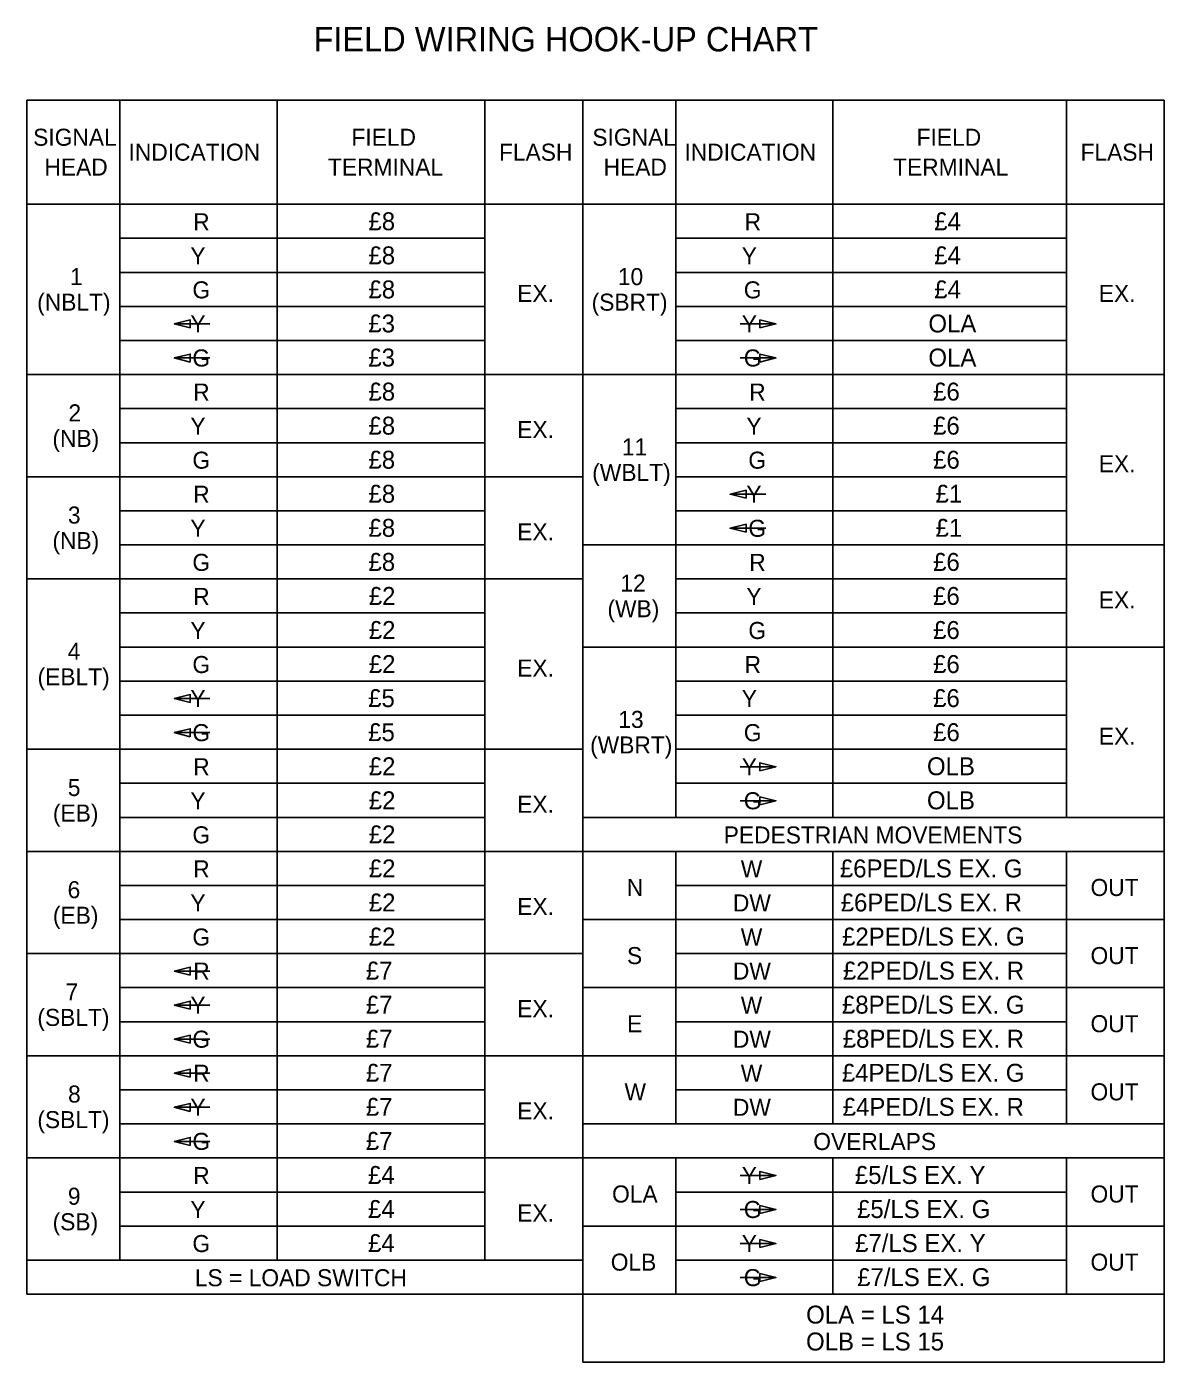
# Model space of a CAD drawing. Extents: x 680 to 2132, y 0 to 656.
# Drawn here: x 1954.6 to 2132.2, y 74.2 to 282.8 of the extents above; entities that cross this region are included whole.
import ezdxf

# ---------------------------------------------------------------- set-up
doc = ezdxf.new("R2010")
doc.units = 0
for name, color, linetype in [('SH_Data', 7, 'Continuous'), ('SH_Text', 7, 'Continuous'), ('ST_Text', 7, 'Continuous')]:
    doc.layers.add(name, color=color, linetype=linetype)

msp = doc.modelspace()

# ---------------------------------------------------------------- linework, layer by layer
at = {"layer": 'SH_Data'}
for p, q in [((1977.6, 236.37), (1983.15, 236.37)), ((2071.56, 236.37), (2066, 236.37)), ((1977.6, 231.05), (1983.15, 231.05)), ((2071.56, 231.05), (2066, 231.05)), ((2064.41, 209.77), (2069.97, 209.77)), ((2064.41, 204.45), (2069.97, 204.45)), ((1977.6, 177.85), (1983.15, 177.85)), ((1977.6, 172.53), (1983.15, 172.53)), ((2071.56, 167.21), (2066, 167.21)), ((2071.56, 161.89), (2066, 161.89)), ((1977.6, 135.29), (1983.15, 135.29)), ((1977.6, 129.97), (1983.15, 129.97)), ((1977.6, 124.65), (1983.15, 124.65)), ((1977.6, 119.33), (1983.15, 119.33)), ((1977.6, 114.01), (1983.15, 114.01)), ((1977.6, 108.69), (1983.15, 108.69)), ((2071.56, 103.37), (2066, 103.37)), ((2071.56, 98.05), (2066, 98.05)), ((2071.56, 92.73), (2066, 92.73)), ((2071.56, 87.41), (2066, 87.41))]:
    msp.add_line(p, q, dxfattribs=at)
for points in [[(1980.1, 235.74), (1977.6, 236.37), (1980.1, 236.99)], [(2069.06, 235.74), (2071.56, 236.37), (2069.06, 236.99)], [(1980.1, 230.42), (1977.6, 231.05), (1980.1, 231.67)], [(2069.06, 230.42), (2071.56, 231.05), (2069.06, 231.67)], [(2066.91, 209.14), (2064.41, 209.77), (2066.91, 210.39)], [(2066.91, 203.82), (2064.41, 204.45), (2066.91, 205.07)], [(1980.1, 177.22), (1977.6, 177.85), (1980.1, 178.47)], [(1980.1, 171.9), (1977.6, 172.53), (1980.1, 173.15)], [(2069.06, 166.58), (2071.56, 167.21), (2069.06, 167.83)], [(2069.06, 161.26), (2071.56, 161.89), (2069.06, 162.51)], [(1980.1, 134.66), (1977.6, 135.29), (1980.1, 135.91)], [(1980.1, 129.34), (1977.6, 129.97), (1980.1, 130.59)], [(1980.1, 124.02), (1977.6, 124.65), (1980.1, 125.27)], [(1980.1, 118.7), (1977.6, 119.33), (1980.1, 119.95)], [(1980.1, 113.38), (1977.6, 114.01), (1980.1, 114.63)], [(1980.1, 108.06), (1977.6, 108.69), (1980.1, 109.31)], [(2069.06, 102.74), (2071.56, 103.37), (2069.06, 103.99)], [(2069.06, 97.42), (2071.56, 98.05), (2069.06, 98.67)], [(2069.06, 92.1), (2071.56, 92.73), (2069.06, 93.35)], [(2069.06, 86.78), (2071.56, 87.41), (2069.06, 88.03)]]:
    msp.add_lwpolyline(points, close=True, dxfattribs=at)
at = {"layer": 'ST_Text'}
for p, q in [((1954.58, 271.34), (2132.21, 271.34)), ((1954.58, 271.34), (1954.58, 84.82)), ((1969.13, 271.34), (1969.13, 90.14)), ((1993.66, 271.34), (1993.66, 90.14)), ((2026.11, 271.34), (2026.11, 90.14)), ((2041.39, 271.34), (2041.39, 74.18)), ((2055.95, 271.34), (2055.95, 159.3)), ((2080.47, 271.34), (2080.47, 159.3)), ((2116.92, 271.34), (2116.92, 159.3)), ((2132.21, 271.34), (2132.21, 74.18)), ((1954.58, 255.06), (2132.21, 255.06)), ((1969.13, 249.74), (2026.11, 249.74)), ((2055.95, 249.74), (2116.92, 249.74)), ((1969.13, 244.42), (2026.11, 244.42)), ((2055.95, 244.42), (2116.92, 244.42)), ((1969.13, 239.1), (2026.11, 239.1)), ((2055.95, 239.1), (2116.92, 239.1)), ((1969.13, 233.78), (2026.11, 233.78)), ((2055.95, 233.78), (2116.92, 233.78)), ((1954.58, 228.46), (2132.21, 228.46)), ((1969.13, 223.14), (2026.11, 223.14)), ((2055.95, 223.14), (2116.92, 223.14)), ((1969.13, 217.82), (2026.11, 217.82)), ((2055.95, 217.82), (2116.92, 217.82)), ((1954.58, 212.5), (2041.39, 212.5)), ((2055.95, 212.5), (2116.92, 212.5)), ((1969.13, 207.18), (2026.11, 207.18)), ((2055.95, 207.18), (2116.92, 207.18)), ((1969.13, 201.86), (2026.11, 201.86)), ((2041.39, 201.86), (2132.21, 201.86)), ((1954.58, 196.54), (2041.39, 196.54)), ((2055.95, 196.54), (2116.92, 196.54)), ((1969.13, 191.22), (2026.11, 191.22)), ((2055.95, 191.22), (2116.92, 191.22)), ((1969.13, 185.9), (2026.11, 185.9)), ((2041.39, 185.9), (2132.21, 185.9)), ((1969.13, 180.58), (2026.11, 180.58)), ((2055.95, 180.58), (2116.92, 180.58)), ((1969.13, 175.26), (2026.11, 175.26)), ((2055.95, 175.26), (2116.92, 175.26)), ((1954.58, 169.94), (2041.39, 169.94)), ((2055.95, 169.94), (2116.92, 169.94)), ((1969.13, 164.62), (2026.11, 164.62)), ((2055.95, 164.62), (2116.92, 164.62)), ((1969.13, 159.3), (2026.11, 159.3)), ((2041.39, 159.3), (2132.21, 159.3)), ((1954.58, 153.98), (2041.39, 153.98)), ((2041.39, 153.98), (2132.21, 153.98)), ((2055.95, 153.98), (2055.95, 111.42)), ((2080.47, 153.98), (2080.47, 111.42)), ((2116.92, 153.98), (2116.92, 111.42)), ((1969.13, 148.66), (2026.11, 148.66)), ((2055.95, 148.66), (2116.92, 148.66)), ((1969.13, 143.34), (2026.11, 143.34)), ((2041.39, 143.34), (2132.21, 143.34)), ((1954.58, 138.02), (2041.39, 138.02)), ((2055.95, 138.02), (2116.92, 138.02)), ((1969.13, 132.7), (2026.11, 132.7)), ((2041.39, 132.7), (2132.21, 132.7)), ((1969.13, 127.38), (2026.11, 127.38)), ((2055.95, 127.38), (2116.92, 127.38)), ((1954.58, 122.06), (2041.39, 122.06)), ((2041.39, 122.06), (2128.21, 122.06)), ((2041.39, 122.06), (2132.21, 122.06)), ((1969.13, 116.74), (2026.11, 116.74)), ((2055.95, 116.74), (2116.92, 116.74)), ((1969.13, 111.42), (2026.11, 111.42)), ((2041.39, 111.42), (2132.21, 111.42)), ((1954.58, 106.1), (2041.39, 106.1)), ((2041.39, 106.1), (2132.21, 106.1)), ((2055.95, 106.1), (2055.95, 84.82)), ((2080.47, 106.1), (2080.47, 84.82)), ((2116.92, 106.1), (2116.92, 84.82)), ((1969.13, 100.78), (2026.11, 100.78)), ((2055.95, 100.78), (2116.92, 100.78)), ((1969.13, 95.46), (2026.11, 95.46)), ((2041.39, 95.46), (2132.21, 95.46)), ((1954.58, 90.14), (2041.39, 90.14)), ((2055.95, 90.14), (2116.92, 90.14)), ((1954.58, 84.82), (2041.39, 84.82)), ((2041.39, 84.82), (2132.21, 84.82)), ((2041.39, 74.18), (2132.21, 74.18))]:
    msp.add_line(p, q, dxfattribs=at)

# ---------------------------------------------------------------- texts
at = {"layer": 'SH_Text'}
for s, height, p in [('FIELD WIRING HOOK-UP CHART', 3.8, (1999.36, 278.94)), ('£8', 2.8, (2007.94, 251)), ('£4', 2.8, (2096.28, 251)), ('£8', 2.8, (2007.94, 245.68)), ('£4', 2.8, (2096.28, 245.68)), ('£8', 2.8, (2007.94, 240.36)), ('£4', 2.8, (2096.28, 240.36)), ('£3', 2.8, (2007.92, 235.04)), ('OLA', 2.8, (2095.37, 235.04)), ('£3', 2.8, (2007.92, 229.72)), ('OLA', 2.8, (2095.37, 229.72)), ('£8', 2.8, (2007.94, 224.4)), ('£6', 2.8, (2096.11, 224.4)), ('£8', 2.8, (2007.94, 219.08)), ('£6', 2.8, (2096.11, 219.08)), ('£8', 2.8, (2007.94, 213.76)), ('£6', 2.8, (2096.11, 213.76)), ('£8', 2.8, (2007.94, 208.44)), ('£1', 2.8, (2096.49, 208.44)), ('£8', 2.8, (2007.94, 203.12)), ('£1', 2.8, (2096.49, 203.12)), ('£8', 2.8, (2007.94, 197.8)), ('£6', 2.8, (2096.11, 197.8)), ('£2', 2.8, (2007.99, 192.48)), ('£6', 2.8, (2096.11, 192.48)), ('£2', 2.8, (2007.99, 187.16)), ('£6', 2.8, (2096.11, 187.16)), ('£2', 2.8, (2007.99, 181.84)), ('£6', 2.8, (2096.11, 181.84)), ('£5', 2.8, (2007.89, 176.52)), ('£6', 2.8, (2096.11, 176.52)), ('£5', 2.8, (2007.89, 171.2)), ('£6', 2.8, (2096.11, 171.2)), ('£2', 2.8, (2007.99, 165.88)), ('OLB', 2.8, (2095.15, 165.88)), ('£2', 2.8, (2007.99, 160.56)), ('OLB', 2.8, (2095.15, 160.56)), ('£2', 2.8, (2007.99, 155.24)), ('£2', 2.8, (2007.99, 149.92)), ('£6PED/LS EX. G', 2.8, (2081.55, 149.92)), ('£2', 2.8, (2007.99, 144.6)), ('£6PED/LS EX. R', 2.8, (2081.68, 144.6)), ('£2', 2.8, (2007.99, 139.28)), ('£2PED/LS EX. G', 2.8, (2081.89, 139.28)), ('£7', 2.8, (2007.53, 133.96)), ('£2PED/LS EX. R', 2.8, (2082.02, 133.96)), ('£7', 2.8, (2007.53, 128.64)), ('£8PED/LS EX. G', 2.8, (2081.87, 128.64)), ('£7', 2.8, (2007.53, 123.32)), ('£8PED/LS EX. R', 2.8, (2082, 123.32)), ('£7', 2.8, (2007.53, 118)), ('£4PED/LS EX. G', 2.8, (2081.86, 118)), ('£7', 2.8, (2007.53, 112.68)), ('£4PED/LS EX. R', 2.8, (2081.99, 112.68)), ('£7', 2.8, (2007.53, 107.36)), ('£4', 2.8, (2007.87, 102.04)), ('£5/LS EX. Y', 2.8, (2083.89, 102.04)), ('£4', 2.8, (2007.87, 96.72)), ('£5/LS EX. G', 2.8, (2084.23, 96.72)), ('£4', 2.8, (2007.87, 91.4)), ('£7/LS EX. Y', 2.8, (2083.92, 91.4)), ('£7/LS EX. G', 2.8, (2084.25, 86.08)), ('OLA = LS 14', 2.8, (2076.28, 80.23)), ('OLB = LS 15', 2.8, (2076.27, 76.03))]:
    msp.add_text(s, height=height, dxfattribs=at).set_placement(p)
at = {"layer": 'ST_Text'}
for s, p in [('SIGNAL', (1955.58, 264.2)), ('FIELD', (2005.28, 264.2)), ('SIGNAL', (2042.9, 264.2)), ('FIELD', (2093.53, 264.2)), ('INDICATION', (1970.47, 261.87)), ('FLASH', (2028.32, 261.87)), ('INDICATION', (2057.28, 261.87)), ('FLASH', (2119.13, 261.87)), ('HEAD', (1957.34, 259.54)), ('TERMINAL', (2001.61, 259.54)), ('HEAD', (2044.66, 259.54)), ('TERMINAL', (2089.86, 259.54)), ('R', (1980.57, 251)), ('R', (2066.67, 251)), ('Y', (1980.13, 245.68)), ('Y', (2066.23, 245.68)), ('1', (1961.33, 242.43)), ('10', (2046.88, 242.43)), ('G', (1980.45, 240.36)), ('EX.', (2031.17, 239.81)), ('G', (2066.55, 240.36)), ('EX.', (2121.98, 239.81)), ('(NBLT)', (1956.21, 238.44)), ('(SBRT)', (2042.79, 238.44)), ('Y', (1980.13, 235.04)), ('Y', (2066.23, 235.04)), ('G', (1980.45, 229.72)), ('G', (2066.55, 229.72)), ('R', (1980.57, 224.4)), ('R', (2067.39, 224.4)), ('2', (1961.09, 221.15)), ('Y', (1980.13, 219.08)), ('EX.', (2031.17, 218.53)), ('Y', (2066.95, 219.08)), ('(NB)', (1958.59, 217.16)), ('11', (2047.51, 215.83)), ('G', (1980.45, 213.76)), ('G', (2067.26, 213.76)), ('EX.', (2121.98, 213.21)), ('(WBLT)', (2042.88, 211.84)), ('R', (1980.57, 208.44)), ('Y', (2066.95, 208.44)), ('3', (1961.01, 205.19)), ('Y', (1980.13, 203.12)), ('EX.', (2031.17, 202.57)), ('G', (2067.26, 203.12)), ('(NB)', (1958.59, 201.2)), ('G', (1980.45, 197.8)), ('R', (2067.39, 197.8)), ('12', (2047.27, 194.55)), ('R', (1980.57, 192.48)), ('Y', (2066.95, 192.48)), ('EX.', (2121.98, 191.93)), ('(WB)', (2045.26, 190.56)), ('G', (2067.26, 187.16)), ('Y', (1980.13, 187.16)), ('4', (1960.97, 183.91)), ('G', (1980.45, 181.84)), ('EX.', (2031.17, 181.29)), ('R', (2066.67, 181.84)), ('(EBLT)', (1956.27, 179.92)), ('Y', (1980.13, 176.52)), ('Y', (2066.23, 176.52)), ('13', (2046.95, 173.27)), ('G', (1980.45, 171.2)), ('G', (2066.55, 171.2)), ('EX.', (2121.98, 170.65)), ('(WBRT)', (2042.55, 169.28)), ('R', (1980.57, 165.88)), ('Y', (2066.23, 165.88)), ('5', (1960.99, 162.63)), ('Y', (1980.13, 160.56)), ('G', (2066.55, 160.56)), ('(EB)', (1958.66, 158.64)), ('EX.', (2031.17, 160.01)), ('G', (1980.45, 155.24)), ('PEDESTRIAN MOVEMENTS', (2063.41, 155.22)), ('R', (1980.57, 149.92)), ('W', (2066.08, 149.92)), ('6', (1960.96, 146.67)), ('N', (2048.27, 147.02)), ('OUT', (2120.69, 147.02)), ('Y', (1980.13, 144.6)), ('EX.', (2031.17, 144.05)), ('DW', (2064.85, 144.6)), ('(EB)', (1958.66, 142.68)), ('G', (1980.45, 139.28)), ('W', (2066.08, 139.28)), ('S', (2048.31, 136.38)), ('OUT', (2120.69, 136.38)), ('R', (1980.57, 133.96)), ('DW', (2064.85, 133.96)), ('7', (1960.65, 130.71)), ('(SBLT)', (1956.24, 126.72)), ('Y', (1980.13, 128.64)), ('EX.', (2031.17, 128.09)), ('W', (2066.08, 128.64)), ('E', (2048.33, 125.74)), ('OUT', (2120.69, 125.74)), ('G', (1980.45, 123.32)), ('DW', (2064.85, 123.32)), ('R', (1980.57, 118)), ('W', (2066.08, 118)), ('8', (1961.03, 114.75)), ('W', (2047.92, 115.1)), ('OUT', (2120.69, 115.1)), ('Y', (1980.13, 112.68)), ('EX.', (2031.17, 112.13)), ('DW', (2064.85, 112.68)), ('(SBLT)', (1956.24, 110.76)), ('G', (1980.45, 107.36)), ('OVERLAPS', (2077.4, 107.34)), ('R', (1980.57, 102.04)), ('Y', (2066.23, 102.04)), ('9', (1961, 98.79)), ('OLA', (2045.98, 99.14)), ('OUT', (2120.69, 99.14)), ('Y', (1980.13, 96.72)), ('EX.', (2031.17, 96.17)), ('G', (2066.55, 96.72)), ('(SB)', (1958.62, 94.8)), ('G', (1980.45, 91.4)), ('Y', (2066.23, 91.4)), ('OLB', (2045.77, 88.5)), ('OUT', (2120.69, 88.5)), ('LS = LOAD SWITCH', (1980.83, 86.06)), ('G', (2066.55, 86.08))]:
    msp.add_text(s, height=2.66, dxfattribs=at).set_placement(p)

doc.saveas('drawing.dxf')
